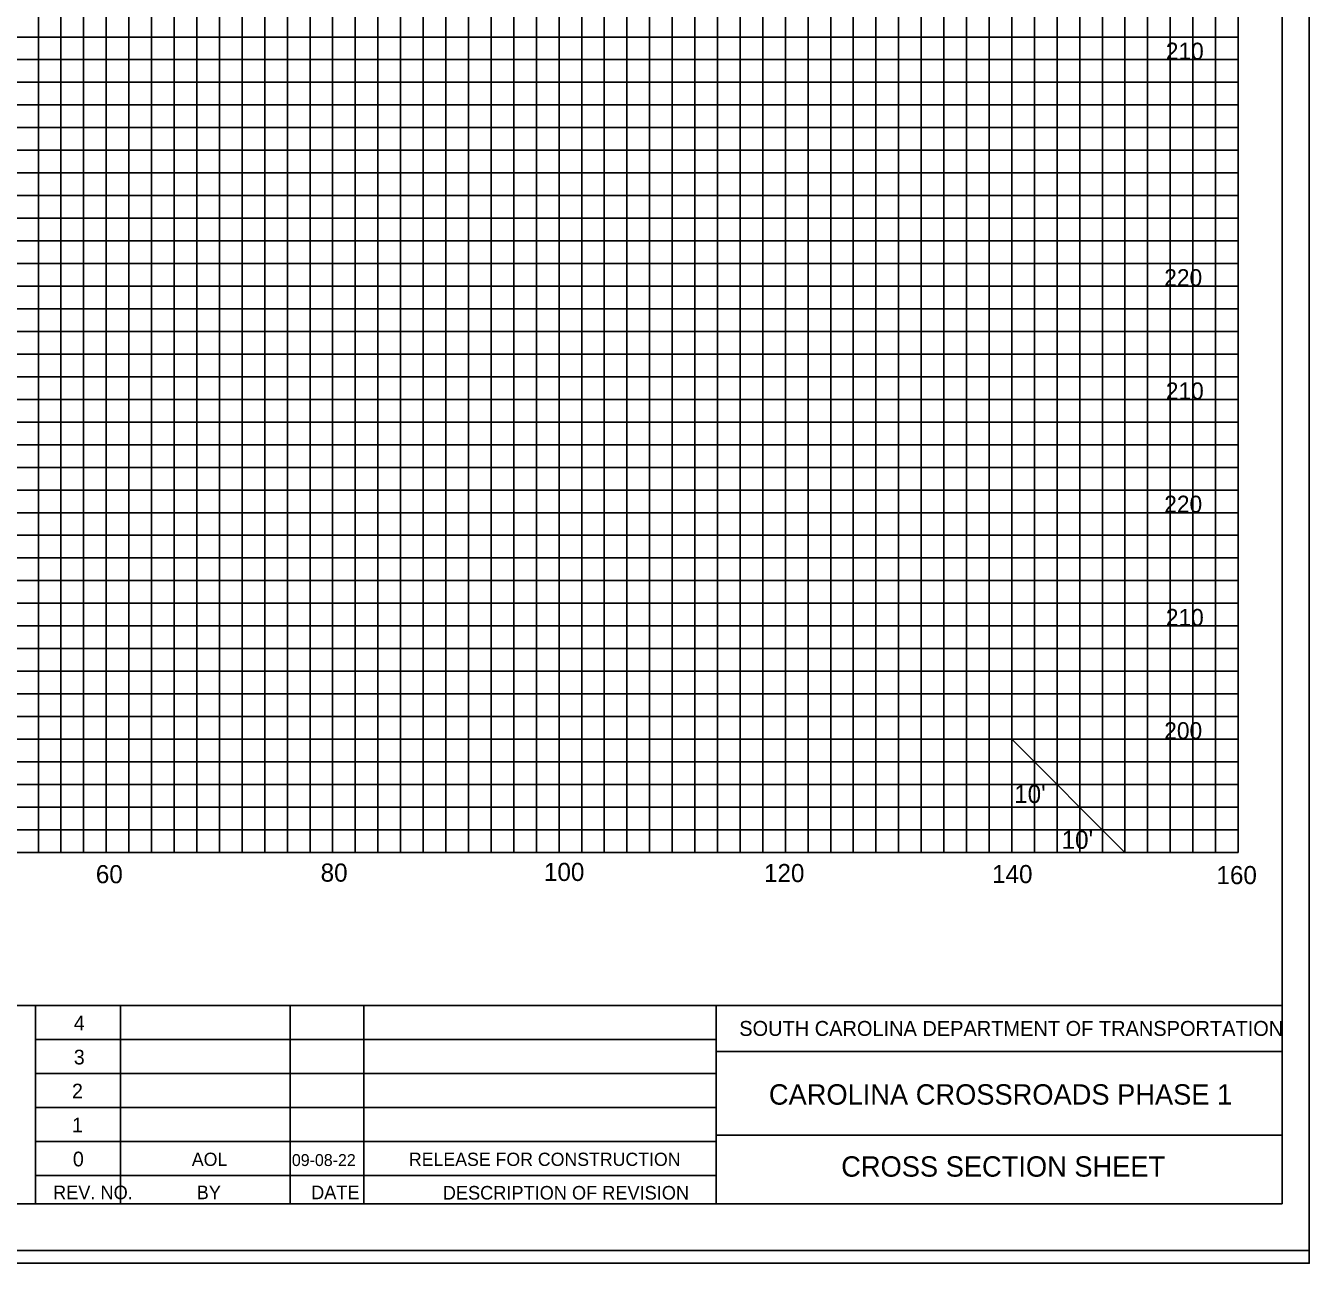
# Model space of a CAD drawing. Extents: x 967 to 1326, y 964 to 2584.
# Drawn here: x 1212.9 to 1326.3, y 963.7 to 1073 of the extents above; entities that cross this region are included whole.
import ezdxf

# ---------------------------------------------------------------- set-up
doc = ezdxf.new("R2010")
doc.units = 0
for name, color, linetype in [('Default', 7, 'Continuous'), ('RD_GPK_XS_Cell', 7, 'Continuous'), ('RD_SHT_Misc1', 7, 'Continuous'), ('RD_XS_ExGround', 7, 'Continuous'), ('RD_XS_ExPaveRet', 7, 'Continuous'), ('RD_XS_Misc_Line', 7, 'Continuous'), ('RD_XS_TX_Elev_EX', 7, 'Continuous')]:
    doc.layers.add(name, color=color, linetype=linetype)

msp = doc.modelspace()

# ---------------------------------------------------------------- linework, layer by layer
at = {"layer": 'RD_GPK_XS_Cell'}
for p, q in [((1220, 1000), (1220, 1170)), ((1230, 1000), (1230, 1170)), ((1240, 1000), (1240, 1170)), ((1250, 1000), (1250, 1170)), ((1260, 1000), (1260, 1170)), ((1270, 1000), (1270, 1170)), ((1280, 1000), (1280, 1170)), ((1290, 1000), (1290, 1170)), ((1300, 1000), (1300, 1170)), ((1310, 1000), (1310, 1170)), ((1320, 1000), (1320, 1170)), ((1000, 1070), (1320, 1070)), ((1000, 1060), (1320, 1060)), ((1000, 1050), (1320, 1050)), ((1000, 1040), (1320, 1040)), ((1000, 1030), (1320, 1030)), ((1000, 1020), (1320, 1020)), ((1000, 1010), (1320, 1010)), ((1000, 1000), (1320, 1000))]:
    msp.add_line(p, q, dxfattribs=at)
at = {"layer": 'RD_XS_ExGround'}
for p, q in [((1214, 1000), (1214, 1170)), ((1216, 1000), (1216, 1170)), ((1218, 1000), (1218, 1170)), ((1222, 1000), (1222, 1170)), ((1224, 1000), (1224, 1170)), ((1226, 1000), (1226, 1170)), ((1228, 1000), (1228, 1170)), ((1232, 1000), (1232, 1170)), ((1234, 1000), (1234, 1170)), ((1236, 1000), (1236, 1170)), ((1238, 1000), (1238, 1170)), ((1242, 1000), (1242, 1170)), ((1244, 1000), (1244, 1170)), ((1246, 1000), (1246, 1170)), ((1248, 1000), (1248, 1170)), ((1252, 1000), (1252, 1170)), ((1254, 1000), (1254, 1170)), ((1256, 1000), (1256, 1170)), ((1258, 1000), (1258, 1170)), ((1262, 1000), (1262, 1170)), ((1264, 1000), (1264, 1170)), ((1266, 1000), (1266, 1170)), ((1268, 1000), (1268, 1170)), ((1272, 1000), (1272, 1170)), ((1274, 1000), (1274, 1170)), ((1276, 1000), (1276, 1170)), ((1278, 1000), (1278, 1170)), ((1282, 1000), (1282, 1170)), ((1284, 1000), (1284, 1170)), ((1286, 1000), (1286, 1170)), ((1288, 1000), (1288, 1170)), ((1292, 1000), (1292, 1170)), ((1294, 1000), (1294, 1170)), ((1296, 1000), (1296, 1170)), ((1298, 1000), (1298, 1170)), ((1302, 1000), (1302, 1170)), ((1304, 1000), (1304, 1170)), ((1306, 1000), (1306, 1170)), ((1308, 1000), (1308, 1170)), ((1312, 1000), (1312, 1170)), ((1314, 1000), (1314, 1170)), ((1316, 1000), (1316, 1170)), ((1318, 1000), (1318, 1170)), ((1000, 1072), (1320, 1072)), ((1000, 1068), (1320, 1068)), ((1000, 1066), (1320, 1066)), ((1000, 1064), (1320, 1064)), ((1000, 1062), (1320, 1062)), ((1000, 1058), (1320, 1058)), ((1000, 1056), (1320, 1056)), ((1000, 1054), (1320, 1054)), ((1000, 1052), (1320, 1052)), ((1000, 1048), (1320, 1048)), ((1000, 1046), (1320, 1046)), ((1000, 1044), (1320, 1044)), ((1000, 1042), (1320, 1042)), ((1000, 1038), (1320, 1038)), ((1000, 1036), (1320, 1036)), ((1000, 1034), (1320, 1034)), ((1000, 1032), (1320, 1032)), ((1000, 1028), (1320, 1028)), ((1000, 1026), (1320, 1026)), ((1000, 1024), (1320, 1024)), ((1000, 1022), (1320, 1022)), ((1000, 1018), (1320, 1018)), ((1000, 1016), (1320, 1016)), ((1000, 1014), (1320, 1014)), ((1000, 1012), (1320, 1012)), ((1000, 1008), (1320, 1008)), ((1000, 1006), (1320, 1006)), ((1000, 1004), (1320, 1004)), ((1000, 1002), (1320, 1002))]:
    msp.add_line(p, q, dxfattribs=at)
at = {"layer": 'RD_XS_ExPaveRet'}
for points in [[(967.41, 963.72), (1326.28, 963.72), (1326.28, 1183.72), (967.41, 1183.72)], [(988.52, 964.84), (1326.28, 964.84), (1326.28, 1182.6), (988.52, 1182.6)]]:
    msp.add_lwpolyline(points, close=True, dxfattribs=at)
at = {"layer": 'RD_XS_Misc_Line'}
msp.add_line((1300, 1010), (1310, 1000), dxfattribs=at)
at = {"layer": 'RD_XS_TX_Elev_EX'}
for p, q in [((1323.89, 1178.46), (1323.89, 968.98)), ((996.11, 986.49), (1323.89, 986.49)), ((1213.76, 968.94), (1213.76, 986.49)), ((1221.26, 968.95), (1221.26, 986.48)), ((1236.26, 968.95), (1236.26, 986.48)), ((1242.76, 968.95), (1242.76, 986.48)), ((1273.88, 968.98), (1273.88, 986.49)), ((1213.76, 983.48), (1273.88, 983.48)), ((1323.93, 982.43), (1273.88, 982.43)), ((1213.76, 980.48), (1273.88, 980.48)), ((1213.76, 977.48), (1273.88, 977.48)), ((1213.76, 974.48), (1273.88, 974.48)), ((1323.89, 975.04), (1273.88, 975.04)), ((1213.76, 971.48), (1273.88, 971.48)), ((1323.89, 968.98), (996.11, 968.98))]:
    msp.add_line(p, q, dxfattribs=at)

# ---------------------------------------------------------------- texts
at = {"layer": 'Default'}
for s, p in [('210', (1313.61, 1070)), ('220', (1313.47, 1050)), ('210', (1313.61, 1040)), ('220', (1313.47, 1030)), ('210', (1313.61, 1020)), ('200', (1313.47, 1010))]:
    msp.add_text(s, height=1.5, dxfattribs=at).set_placement(p)
at = {"layer": 'RD_SHT_Misc1'}
for s, height, p in [('AOL', 1.17, (1227.56, 972.32)), ('09-08-22', 1.053, (1236.4, 972.31)), ('RELEASE FOR CONSTRUCTION', 1.17, (1246.74, 972.32))]:
    msp.add_text(s, height=height, dxfattribs=at).set_placement(p)
at = {"layer": 'RD_XS_Misc_Line'}
for s, height, p in [("10'", 1.6, (1300.21, 1004.36)), ("10'", 1.6, (1304.4, 1000.32)), ('100', 1.6, (1258.67, 997.48)), ('60', 1.6, (1219.08, 997.28)), ('80', 1.6, (1238.94, 997.42)), ('120', 1.6, (1278.11, 997.38)), ('140', 1.6, (1298.26, 997.29)), ('160', 1.6, (1318.08, 997.2)), ('4', 1.3, (1217.13, 984.28)), ('SOUTH CAROLINA DEPARTMENT OF TRANSPORTATION', 1.32, (1275.92, 983.8)), ('3', 1.3, (1217.13, 981.28)), ('2', 1.3, (1216.97, 978.28)), ('1', 1.3, (1216.97, 975.28)), ('0', 1.3, (1217.05, 972.28)), ('REV. NO.', 1.2, (1215.3, 969.38)), ('BY', 1.2, (1227.99, 969.38)), ('DATE', 1.2, (1238.1, 969.38)), ('DESCRIPTION OF REVISION', 1.2, (1249.73, 969.35))]:
    msp.add_text(s, height=height, dxfattribs=at).set_placement(p)
for s, p in [('CAROLINA CROSSROADS PHASE 1', (1278.54, 977.73)), ('CROSS SECTION SHEET', (1284.93, 971.37))]:
    msp.add_text(s, height=1.8, rotation=0, dxfattribs=at).set_placement(p)

doc.saveas('drawing.dxf')
